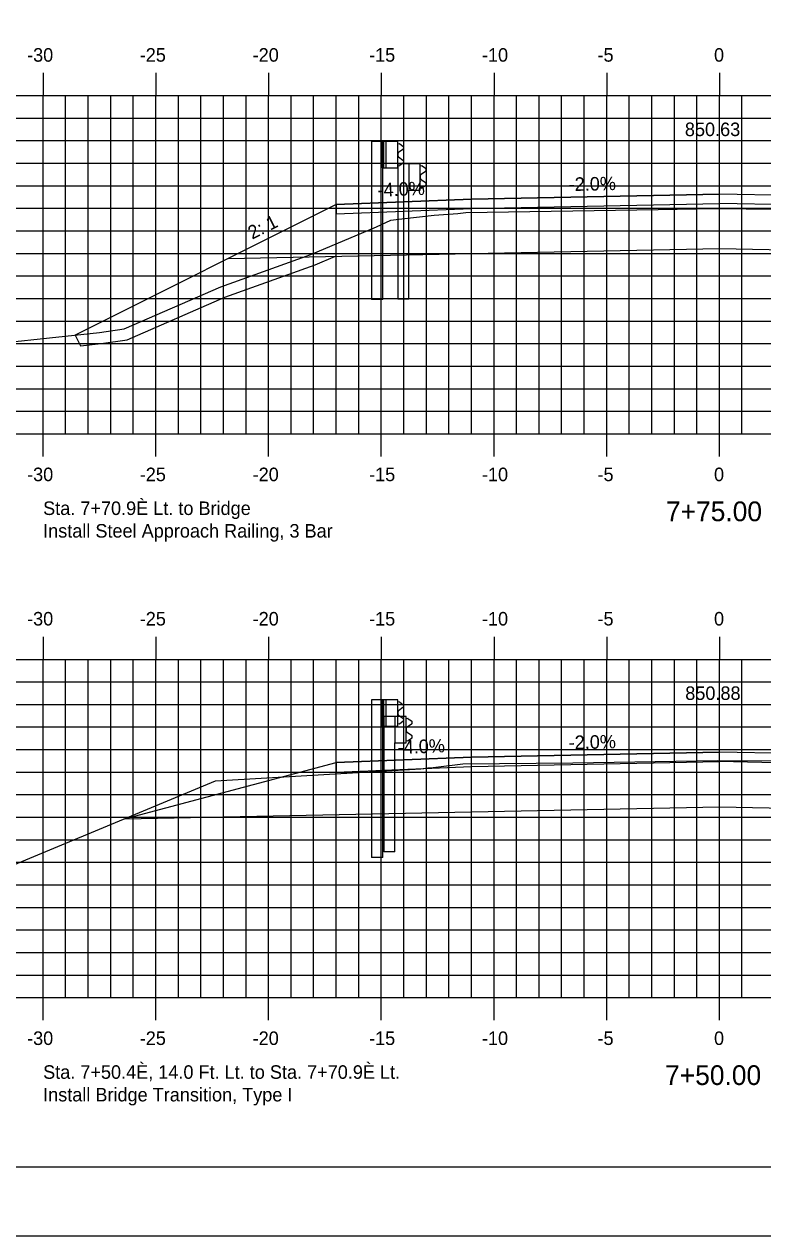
# Model space of a CAD drawing. Extents: x 2194256 to 2194747, y 863888 to 863998.
# Drawn here: x 2194445.9 to 2194478.7, y 863888.4 to 863942.1 of the extents above; entities that cross this region are included whole.
import ezdxf

# ---------------------------------------------------------------- set-up
doc = ezdxf.new("R2010")
doc.units = 0
for name, color, linetype in [('ANNOTATION', 7, 'Continuous'), ('BORDER', 7, 'Continuous'), ('D_Guardrail_Beam_Lt', 7, 'Continuous'), ('H_V ANNOTATION', 7, 'Continuous'), ('MAJOR', 7, 'Continuous'), ('MINOR', 7, 'Continuous'), ('PLOT BOUNDARY', 7, 'Continuous'), ('S_Guardrail_Beam', 7, 'Continuous'), ('S_Roadway_Centerline', 7, 'Continuous'), ('TEMPLATE', 7, 'Continuous')]:
    doc.layers.add(name, color=color, linetype=linetype)

msp = doc.modelspace()

# ---------------------------------------------------------------- linework, layer by layer
at = {"layer": 'BORDER'}
msp.add_lwpolyline([(2194401.743, 863891.446), (2194561.743, 863891.446), (2194561.743, 863996.446), (2194401.743, 863996.446)], close=True, dxfattribs=at)
at = {"layer": 'D_Guardrail_Beam_Lt'}
for p, q in [((2194461.314, 863936.902), (2194461.314, 863929.902)), ((2194461.784, 863936.902), (2194461.314, 863936.902)), ((2194462.472, 863936.902), (2194461.784, 863936.902)), ((2194461.784, 863936.902), (2194461.784, 863935.736)), ((2194461.847, 863936.902), (2194461.847, 863935.736)), ((2194461.951, 863936.902), (2194461.951, 863935.736)), ((2194462.472, 863935.736), (2194462.472, 863936.902)), ((2194462.472, 863936.819), (2194462.546, 863936.805)), ((2194462.562, 863936.798), (2194462.705, 863936.698)), ((2194462.476, 863936.354), (2194462.476, 863936.284)), ((2194462.705, 863936.555), (2194462.51, 863936.419)), ((2194461.784, 863935.736), (2194462.472, 863935.736)), ((2194461.805, 863929.902), (2194461.805, 863935.736)), ((2194462.546, 863935.834), (2194462.472, 863935.819)), ((2194462.51, 863936.22), (2194462.705, 863936.083)), ((2194462.705, 863935.94), (2194462.562, 863935.84)), ((2194461.805, 863929.902), (2194461.314, 863929.902)), ((2194461.314, 863912.152), (2194461.314, 863905.152)), ((2194461.784, 863912.152), (2194461.314, 863912.152)), ((2194462.472, 863912.152), (2194461.784, 863912.152)), ((2194461.784, 863912.152), (2194461.784, 863910.986)), ((2194461.847, 863912.152), (2194461.847, 863910.986)), ((2194461.951, 863912.152), (2194461.951, 863910.986)), ((2194462.472, 863910.986), (2194462.472, 863912.152)), ((2194462.472, 863912.069), (2194462.546, 863912.055)), ((2194462.476, 863911.604), (2194462.476, 863911.534)), ((2194462.705, 863911.805), (2194462.51, 863911.669)), ((2194462.562, 863912.048), (2194462.705, 863911.948)), ((2194462.546, 863911.084), (2194462.472, 863911.069)), ((2194462.51, 863911.47), (2194462.705, 863911.333)), ((2194462.705, 863911.19), (2194462.562, 863911.09)), ((2194461.784, 863910.986), (2194462.472, 863910.986)), ((2194461.805, 863905.152), (2194461.805, 863910.986)), ((2194461.805, 863905.152), (2194461.314, 863905.152))]:
    msp.add_line(p, q, dxfattribs=at)
for centre, major_axis, start_param, end_param in [((2194462.538, 863936.764), (0.0417, 0), 0.959931, 1.376053), ((2194462.555, 863936.354), (-0.0789, 0), 5.323254, 6.283185), ((2194462.555, 863936.284), (-0.0789, 0), 6.283185, 7.243116), ((2194462.655, 863936.626), (0.0877, 0), 5.323254, 7.243116), ((2194462.538, 863935.874), (0.0417, 0), 4.907132, 5.323254), ((2194462.655, 863936.012), (0.0877, 0), 5.323254, 7.243116), ((2194462.555, 863911.604), (-0.0789, 0), 5.323254, 6.283185), ((2194462.555, 863911.534), (-0.0789, 0), 6.283185, 7.243116), ((2194462.538, 863912.014), (0.0417, 0), 0.959931, 1.376053), ((2194462.655, 863911.876), (0.0877, 0), 5.323254, 7.243116), ((2194462.538, 863911.124), (0.0417, 0), 4.907132, 5.323254), ((2194462.655, 863911.262), (0.0877, 0), 5.323254, 7.243116)]:
    msp.add_ellipse(centre, major_axis=major_axis, ratio=0.995501, start_param=start_param, end_param=end_param, dxfattribs=at)
at = {"layer": 'MAJOR'}
for p, q in [((2194446.743, 863939.948), (2194446.743, 863938.946)), ((2194451.743, 863939.948), (2194451.743, 863938.946)), ((2194456.743, 863939.948), (2194456.743, 863938.946)), ((2194461.743, 863939.948), (2194461.743, 863938.946)), ((2194466.743, 863939.948), (2194466.743, 863938.946)), ((2194471.743, 863939.948), (2194471.743, 863938.946)), ((2194476.743, 863939.948), (2194476.743, 863938.946)), ((2194406.743, 863938.946), (2194546.743, 863938.946)), ((2194446.743, 863923.946), (2194446.743, 863938.946)), ((2194451.743, 863923.946), (2194451.743, 863938.946)), ((2194456.743, 863923.946), (2194456.743, 863938.946)), ((2194461.743, 863923.946), (2194461.743, 863938.946)), ((2194466.743, 863923.946), (2194466.743, 863938.946)), ((2194471.743, 863923.946), (2194471.743, 863938.946)), ((2194476.743, 863923.946), (2194476.743, 863938.946)), ((2194406.743, 863933.946), (2194546.743, 863933.946)), ((2194406.743, 863928.946), (2194546.743, 863928.946)), ((2194406.743, 863923.946), (2194546.743, 863923.946)), ((2194446.743, 863922.944), (2194446.743, 863923.946)), ((2194451.743, 863922.944), (2194451.743, 863923.946)), ((2194456.743, 863922.944), (2194456.743, 863923.946)), ((2194461.743, 863922.944), (2194461.743, 863923.946)), ((2194466.743, 863922.944), (2194466.743, 863923.946)), ((2194471.743, 863922.944), (2194471.743, 863923.946)), ((2194476.743, 863922.944), (2194476.743, 863923.946)), ((2194446.743, 863914.948), (2194446.743, 863913.946)), ((2194451.743, 863914.948), (2194451.743, 863913.946)), ((2194456.743, 863914.948), (2194456.743, 863913.946)), ((2194461.743, 863914.948), (2194461.743, 863913.946)), ((2194466.743, 863914.948), (2194466.743, 863913.946)), ((2194471.743, 863914.948), (2194471.743, 863913.946)), ((2194476.743, 863914.948), (2194476.743, 863913.946)), ((2194406.743, 863913.946), (2194546.743, 863913.946)), ((2194446.743, 863898.946), (2194446.743, 863913.946)), ((2194451.743, 863898.946), (2194451.743, 863913.946)), ((2194456.743, 863898.946), (2194456.743, 863913.946)), ((2194461.743, 863898.946), (2194461.743, 863913.946)), ((2194466.743, 863898.946), (2194466.743, 863913.946)), ((2194471.743, 863898.946), (2194471.743, 863913.946)), ((2194476.743, 863898.946), (2194476.743, 863913.946)), ((2194406.743, 863908.946), (2194546.743, 863908.946)), ((2194406.743, 863903.946), (2194546.743, 863903.946)), ((2194406.743, 863898.946), (2194546.743, 863898.946)), ((2194446.743, 863897.944), (2194446.743, 863898.946)), ((2194451.743, 863897.944), (2194451.743, 863898.946)), ((2194456.743, 863897.944), (2194456.743, 863898.946)), ((2194461.743, 863897.944), (2194461.743, 863898.946)), ((2194466.743, 863897.944), (2194466.743, 863898.946)), ((2194471.743, 863897.944), (2194471.743, 863898.946)), ((2194476.743, 863897.944), (2194476.743, 863898.946))]:
    msp.add_line(p, q, dxfattribs=at)
at = {"layer": 'MINOR'}
for p, q in [((2194447.743, 863923.946), (2194447.743, 863938.946)), ((2194448.743, 863923.946), (2194448.743, 863938.946)), ((2194449.743, 863923.946), (2194449.743, 863938.946)), ((2194450.743, 863923.946), (2194450.743, 863938.946)), ((2194452.743, 863923.946), (2194452.743, 863938.946)), ((2194453.743, 863923.946), (2194453.743, 863938.946)), ((2194454.743, 863923.946), (2194454.743, 863938.946)), ((2194455.743, 863923.946), (2194455.743, 863938.946)), ((2194457.743, 863923.946), (2194457.743, 863938.946)), ((2194458.743, 863923.946), (2194458.743, 863938.946)), ((2194459.743, 863923.946), (2194459.743, 863938.946)), ((2194460.743, 863923.946), (2194460.743, 863938.946)), ((2194462.743, 863923.946), (2194462.743, 863938.946)), ((2194463.743, 863923.946), (2194463.743, 863938.946)), ((2194464.743, 863923.946), (2194464.743, 863938.946)), ((2194465.743, 863923.946), (2194465.743, 863938.946)), ((2194467.743, 863923.946), (2194467.743, 863938.946)), ((2194468.743, 863923.946), (2194468.743, 863938.946)), ((2194469.743, 863923.946), (2194469.743, 863938.946)), ((2194470.743, 863923.946), (2194470.743, 863938.946)), ((2194472.743, 863923.946), (2194472.743, 863938.946)), ((2194473.743, 863923.946), (2194473.743, 863938.946)), ((2194474.743, 863923.946), (2194474.743, 863938.946)), ((2194475.743, 863923.946), (2194475.743, 863938.946)), ((2194477.743, 863923.946), (2194477.743, 863938.946)), ((2194406.743, 863937.946), (2194546.743, 863937.946)), ((2194406.743, 863936.946), (2194546.743, 863936.946)), ((2194406.743, 863935.946), (2194546.743, 863935.946)), ((2194406.743, 863934.946), (2194546.743, 863934.946)), ((2194406.743, 863932.946), (2194546.743, 863932.946)), ((2194406.743, 863931.946), (2194546.743, 863931.946)), ((2194406.743, 863930.946), (2194546.743, 863930.946)), ((2194406.743, 863929.946), (2194546.743, 863929.946)), ((2194406.743, 863927.946), (2194546.743, 863927.946)), ((2194406.743, 863926.946), (2194546.743, 863926.946)), ((2194406.743, 863925.946), (2194546.743, 863925.946)), ((2194406.743, 863924.946), (2194546.743, 863924.946)), ((2194447.743, 863898.946), (2194447.743, 863913.946)), ((2194448.743, 863898.946), (2194448.743, 863913.946)), ((2194449.743, 863898.946), (2194449.743, 863913.946)), ((2194450.743, 863898.946), (2194450.743, 863913.946)), ((2194452.743, 863898.946), (2194452.743, 863913.946)), ((2194453.743, 863898.946), (2194453.743, 863913.946)), ((2194454.743, 863898.946), (2194454.743, 863913.946)), ((2194455.743, 863898.946), (2194455.743, 863913.946)), ((2194457.743, 863898.946), (2194457.743, 863913.946)), ((2194458.743, 863898.946), (2194458.743, 863913.946)), ((2194459.743, 863898.946), (2194459.743, 863913.946)), ((2194460.743, 863898.946), (2194460.743, 863913.946)), ((2194462.743, 863898.946), (2194462.743, 863913.946)), ((2194463.743, 863898.946), (2194463.743, 863913.946)), ((2194464.743, 863898.946), (2194464.743, 863913.946)), ((2194465.743, 863898.946), (2194465.743, 863913.946)), ((2194467.743, 863898.946), (2194467.743, 863913.946)), ((2194468.743, 863898.946), (2194468.743, 863913.946)), ((2194469.743, 863898.946), (2194469.743, 863913.946)), ((2194470.743, 863898.946), (2194470.743, 863913.946)), ((2194472.743, 863898.946), (2194472.743, 863913.946)), ((2194473.743, 863898.946), (2194473.743, 863913.946)), ((2194474.743, 863898.946), (2194474.743, 863913.946)), ((2194475.743, 863898.946), (2194475.743, 863913.946)), ((2194477.743, 863898.946), (2194477.743, 863913.946)), ((2194406.743, 863912.946), (2194546.743, 863912.946)), ((2194406.743, 863911.946), (2194546.743, 863911.946)), ((2194406.743, 863910.946), (2194546.743, 863910.946)), ((2194406.743, 863909.946), (2194546.743, 863909.946)), ((2194406.743, 863907.946), (2194546.743, 863907.946)), ((2194406.743, 863906.946), (2194546.743, 863906.946)), ((2194406.743, 863905.946), (2194546.743, 863905.946)), ((2194406.743, 863904.946), (2194546.743, 863904.946)), ((2194406.743, 863902.946), (2194546.743, 863902.946)), ((2194406.743, 863901.946), (2194546.743, 863901.946)), ((2194406.743, 863900.946), (2194546.743, 863900.946)), ((2194406.743, 863899.946), (2194546.743, 863899.946))]:
    msp.add_line(p, q, dxfattribs=at)
at = {"layer": 'PLOT BOUNDARY'}
msp.add_lwpolyline([(2194393.65, 863888.387), (2194563.65, 863888.387), (2194563.65, 863998.387), (2194393.65, 863998.387)], close=True, dxfattribs=at)
at = {"layer": 'S_Guardrail_Beam'}
for p, q in [((2194462.48, 863935.919), (2194462.48, 863929.919)), ((2194462.971, 863935.919), (2194462.48, 863935.919)), ((2194463.461, 863935.919), (2194462.971, 863935.919)), ((2194462.971, 863935.919), (2194462.971, 863934.752)), ((2194463.461, 863934.752), (2194463.461, 863935.919)), ((2194463.461, 863935.846), (2194463.543, 863935.832)), ((2194463.56, 863935.825), (2194463.703, 863935.725)), ((2194463.474, 863935.381), (2194463.474, 863935.29)), ((2194463.703, 863935.582), (2194463.508, 863935.446)), ((2194463.508, 863935.226), (2194463.703, 863935.09)), ((2194462.971, 863929.919), (2194462.971, 863934.752)), ((2194462.971, 863934.752), (2194463.461, 863934.752)), ((2194463.543, 863934.84), (2194463.461, 863934.825)), ((2194463.703, 863934.947), (2194463.56, 863934.847)), ((2194462.971, 863929.919), (2194462.48, 863929.919)), ((2194461.859, 863911.409), (2194461.859, 863905.409)), ((2194462.35, 863911.409), (2194461.859, 863911.409)), ((2194462.84, 863911.409), (2194462.35, 863911.409)), ((2194462.35, 863911.409), (2194462.35, 863910.243)), ((2194462.84, 863910.243), (2194462.84, 863911.409)), ((2194462.84, 863911.337), (2194462.922, 863911.322)), ((2194463.082, 863911.072), (2194462.887, 863910.936)), ((2194462.939, 863911.315), (2194463.082, 863911.215)), ((2194462.853, 863910.872), (2194462.853, 863910.781)), ((2194462.887, 863910.716), (2194463.082, 863910.58)), ((2194462.35, 863905.409), (2194462.35, 863910.243)), ((2194462.35, 863910.243), (2194462.84, 863910.243)), ((2194462.922, 863910.33), (2194462.84, 863910.316)), ((2194463.082, 863910.437), (2194462.939, 863910.337)), ((2194462.35, 863905.409), (2194461.859, 863905.409))]:
    msp.add_line(p, q, dxfattribs=at)
for centre, major_axis, start_param, end_param in [((2194463.536, 863935.791), (0.0417, 0), 0.959931, 1.396263), ((2194463.653, 863935.653), (0.0877, 0), 5.323254, 7.243116), ((2194463.553, 863935.381), (-0.0789, 0), 5.323254, 6.283185), ((2194463.553, 863935.29), (-0.0789, 0), 6.283185, 7.243116), ((2194463.536, 863934.881), (0.0417, 0), 4.886922, 5.323254), ((2194463.653, 863935.018), (0.0877, 0), 5.323254, 7.243116), ((2194462.915, 863911.281), (0.0417, 0), 0.959931, 1.396263), ((2194463.032, 863911.144), (0.0877, 0), 5.323254, 7.243116), ((2194462.932, 863910.872), (-0.0789, 0), 5.323254, 6.283185), ((2194462.932, 863910.781), (-0.0789, 0), 6.283185, 7.243116), ((2194463.032, 863910.509), (0.0877, 0), 5.323254, 7.243116), ((2194462.915, 863910.371), (0.0417, 0), 4.886922, 5.323254)]:
    msp.add_ellipse(centre, major_axis=major_axis, ratio=0.995501, start_param=start_param, end_param=end_param, dxfattribs=at)
at = {"layer": 'S_Roadway_Centerline'}
for points in [[(2194442.863, 863927.76), (2194449.251, 863928.439), (2194450.337, 863928.603), (2194454.623, 863930.463), (2194458.623, 863931.901), (2194461.536, 863933.124), (2194462.161, 863933.415), (2194462.515, 863933.466), (2194464.085, 863933.642), (2194465.136, 863933.716), (2194465.493, 863933.756), (2194474.019, 863933.889), (2194476.568, 863933.943), (2194476.586, 863933.943), (2194479.256, 863933.911), (2194488.047, 863933.866), (2194488.748, 863933.828), (2194492.853, 863933.603), (2194494.098, 863933.09), (2194496.246, 863932.361), (2194499.381, 863931.386), (2194500.582, 863931.046), (2194505.6, 863928.851)], [(2194442.413, 863903.585), (2194454.389, 863908.554), (2194463.492, 863909.094), (2194463.809, 863909.13), (2194464.046, 863909.146), (2194465.354, 863909.317), (2194470.233, 863909.359), (2194476.647, 863909.46), (2194483.268, 863909.426), (2194487.992, 863909.437), (2194491.166, 863909.262), (2194494.029, 863909.115), (2194497.76, 863908.092), (2194498.817, 863907.801), (2194503.284, 863905.992)]]:
    msp.add_lwpolyline(points, dxfattribs=at)
at = {"layer": 'TEMPLATE'}
for p, q in [((2194459.743, 863934.116), (2194448.158, 863928.323)), ((2194465.743, 863934.356), (2194459.743, 863934.116)), ((2194465.743, 863934.356), (2194476.743, 863934.576)), ((2194476.743, 863934.576), (2194465.743, 863934.356)), ((2194465.743, 863933.939), (2194476.743, 863934.159)), ((2194487.743, 863934.356), (2194476.743, 863934.576)), ((2194487.743, 863933.939), (2194476.743, 863934.159)), ((2194448.158, 863928.323), (2194448.396, 863927.846)), ((2194465.743, 863909.606), (2194459.743, 863909.366)), ((2194465.743, 863909.606), (2194476.743, 863909.826)), ((2194476.743, 863909.826), (2194465.743, 863909.606)), ((2194465.743, 863909.189), (2194476.743, 863909.409)), ((2194487.743, 863909.606), (2194476.743, 863909.826)), ((2194487.743, 863909.189), (2194476.743, 863909.409)), ((2194450.357, 863906.881), (2194459.743, 863909.366))]:
    msp.add_line(p, q, dxfattribs=at)
for points in [[(2194459.743, 863934.116), (2194459.743, 863934.116), (2194465.743, 863934.356)], [(2194459.743, 863933.699), (2194459.743, 863934.116), (2194459.743, 863933.699), (2194465.743, 863933.939)], [(2194454.958, 863931.723), (2194465.743, 863931.939), (2194476.743, 863932.159), (2194487.743, 863931.939), (2194498.527, 863931.723)], [(2194448.396, 863927.846), (2194449.314, 863927.943), (2194450.476, 863928.118), (2194454.807, 863929.998), (2194458.805, 863931.435), (2194459.718, 863931.819)], [(2194459.743, 863909.366), (2194459.743, 863909.366), (2194465.743, 863909.606)], [(2194459.743, 863908.949), (2194459.743, 863909.366), (2194459.743, 863908.949), (2194465.743, 863909.189)], [(2194450.357, 863906.881), (2194465.743, 863907.189), (2194476.743, 863907.409), (2194487.743, 863907.189), (2194500.982, 863906.924)]]:
    msp.add_lwpolyline(points, dxfattribs=at)

# ---------------------------------------------------------------- texts
at = {"layer": 'ANNOTATION'}
for s, p in [('850.63', (2194475.21, 863937.146)), ('Sta. 7+70.9È Lt. to Bridge', (2194446.743, 863920.346)), ('Install Steel Approach Railing, 3 Bar', (2194446.743, 863919.344)), ('850.88', (2194475.226, 863912.146)), ('Sta. 7+50.4È, 14.0 Ft. Lt. to Sta. 7+70.9È Lt.', (2194446.743, 863895.346)), ('Install Bridge Transition, Type I', (2194446.743, 863894.344))]:
    msp.add_text(s, height=0.6, dxfattribs=at).set_placement(p)
for s, rotation, p in [('-2.0%', 1.1458, (2194470.06, 863934.709)), ('-4.0%', 2.2906, (2194461.588, 863934.457)), ('2: 1', 26.5651, (2194456.017, 863932.551)), ('-2.0%', 1.1458, (2194470.06, 863909.959)), ('-4.0%', 2.2906, (2194462.48, 863909.742))]:
    msp.add_text(s, height=0.6, rotation=rotation, dxfattribs=at).set_placement(p)
at = {"layer": 'H_V ANNOTATION'}
for s, height, p in [('-30', 0.6, (2194446.031, 863940.446)), ('-25', 0.6, (2194451.028, 863940.446)), ('-20', 0.6, (2194456.036, 863940.446)), ('-15', 0.6, (2194461.2, 863940.446)), ('-10', 0.6, (2194466.208, 863940.446)), ('-5', 0.6, (2194471.333, 863940.446)), ('0', 0.6, (2194476.502, 863940.446)), ('-30', 0.6, (2194446.031, 863921.846)), ('-25', 0.6, (2194451.028, 863921.846)), ('-20', 0.6, (2194456.036, 863921.846)), ('-15', 0.6, (2194461.2, 863921.846)), ('-10', 0.6, (2194466.208, 863921.846)), ('-5', 0.6, (2194471.333, 863921.846)), ('0', 0.6, (2194476.502, 863921.846)), ('7+75.00', 0.875, (2194474.37, 863920.071)), ('-30', 0.6, (2194446.031, 863915.446)), ('-25', 0.6, (2194451.028, 863915.446)), ('-20', 0.6, (2194456.036, 863915.446)), ('-15', 0.6, (2194461.2, 863915.446)), ('-10', 0.6, (2194466.208, 863915.446)), ('-5', 0.6, (2194471.333, 863915.446)), ('0', 0.6, (2194476.502, 863915.446)), ('-30', 0.6, (2194446.031, 863896.846)), ('-25', 0.6, (2194451.028, 863896.846)), ('-20', 0.6, (2194456.036, 863896.846)), ('-15', 0.6, (2194461.2, 863896.846)), ('-10', 0.6, (2194466.208, 863896.846)), ('-5', 0.6, (2194471.333, 863896.846)), ('0', 0.6, (2194476.502, 863896.846)), ('7+50.00', 0.875, (2194474.331, 863895.071))]:
    msp.add_text(s, height=height, dxfattribs=at).set_placement(p)

doc.saveas('drawing.dxf')
